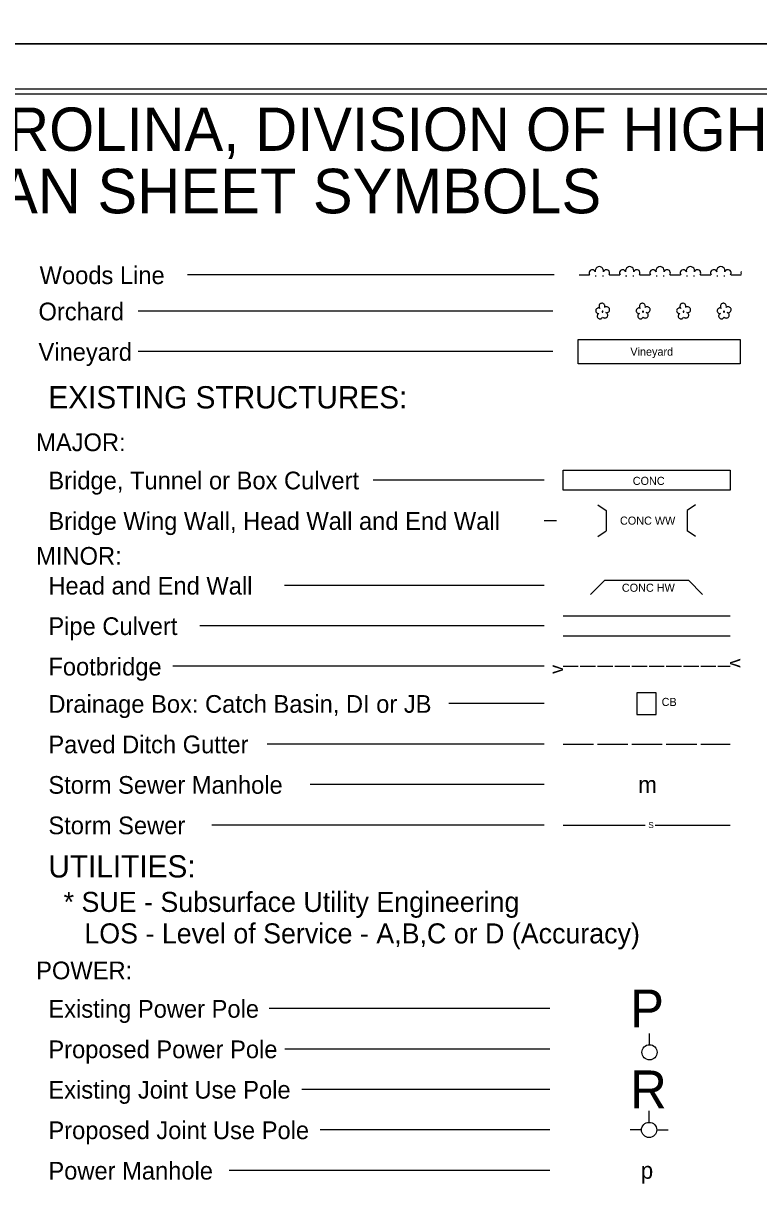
# Model space of a CAD drawing. Extents: x 925297 to 940193, y 663541 to 689899.
# Drawn here: x 932679 to 935584, y 667786 to 672419 of the extents above; entities that cross this region are included whole.
import ezdxf

# ---------------------------------------------------------------- set-up
doc = ezdxf.new("R2010")
doc.units = 0
for name, color, linetype in [('Sheet Cutting Line CELL', 7, 'Continuous'), ('Sheet Plot Border Inside CELL', 7, 'Continuous'), ('Sheet Plot Border Outside CELL', 7, 'Continuous'), ('Sheet Symbology CELL', 7, 'Continuous')]:
    doc.layers.add(name, color=color, linetype=linetype)

msp = doc.modelspace()

# ---------------------------------------------------------------- linework, layer by layer
at = {"layer": 'Sheet Cutting Line CELL'}
msp.add_line((938764.7, 672338.7), (925296.7, 672338.7), dxfattribs=at)
at = {"layer": 'Sheet Plot Border Inside CELL'}
msp.add_lwpolyline([(925400.7, 663720.9), (938728.7, 663720.9), (938728.7, 672159.2), (925400.7, 672159.2)], close=True, dxfattribs=at)
at = {"layer": 'Sheet Plot Border Outside CELL'}
for points in [[(925296.7, 672338.7), (938764.7, 672338.7), (938764.7, 681098.7), (925296.7, 681098.7)], [(925296.7, 663541.3), (938764.7, 663541.3), (938764.7, 672338.7), (925296.7, 672338.7)]]:
    msp.add_lwpolyline(points, close=True, dxfattribs=at)
at = {"layer": 'Sheet Symbology CELL'}
for p, q in [((934776, 671424.9), (933327.4, 671424.9)), ((934875.1, 671424.9), (934915.1, 671424.9)), ((934938.7, 671420.9), (934942.7, 671420.9)), ((934966.7, 671420.9), (934970.7, 671420.9)), ((934995, 671424.9), (935035, 671424.9)), ((935058.6, 671420.9), (935062.6, 671420.9)), ((935086.6, 671420.9), (935090.6, 671420.9)), ((935115, 671424.9), (935155, 671424.9)), ((935178.6, 671420.9), (935182.6, 671420.9)), ((935206.6, 671420.9), (935210.6, 671420.9)), ((935235, 671424.9), (935275, 671424.9)), ((935298.6, 671420.9), (935302.6, 671420.9)), ((935326.5, 671420.9), (935330.5, 671420.9)), ((935354.9, 671424.9), (935394.9, 671424.9)), ((935418.5, 671420.9), (935422.5, 671420.9)), ((935446.5, 671420.9), (935450.5, 671420.9)), ((935474.9, 671424.9), (935514.9, 671424.9)), ((934771.4, 671281.5), (933132.4, 671281.5)), ((934771.4, 671121.5), (933132.4, 671121.5)), ((934736.9, 670613.6), (934061.7, 670613.6)), ((934948.5, 670516.6), (934981.3, 670493.7)), ((935334, 670516.6), (935301.2, 670493.7)), ((934981.3, 670493.7), (934981.3, 670413.7)), ((935301.2, 670493.7), (935301.2, 670413.7)), ((934736.9, 670453.7), (934784.8, 670453.7)), ((934948.5, 670390.8), (934981.3, 670413.7)), ((935334, 670390.8), (935301.2, 670413.7)), ((934736.9, 670197.8), (933710.8, 670197.8)), ((934919.7, 670161.2), (934976.3, 670217.8)), ((934976.3, 670217.8), (935306.2, 670217.8)), ((935306.2, 670217.8), (935362.7, 670161.2)), ((934811.3, 670077.8), (935471.1, 670077.8)), ((934736.9, 670037.9), (933375.8, 670037.9)), ((934811.3, 669997.9), (935471.1, 669997.9)), ((934736.9, 669877.9), (933269.6, 669877.9)), ((934811.3, 669877.9), (934871.3, 669877.9)), ((934879.3, 669877.9), (934939.3, 669877.9)), ((934947.3, 669877.9), (935007.3, 669877.9)), ((935015.3, 669877.9), (935075.2, 669877.9)), ((935083.2, 669877.9), (935143.2, 669877.9)), ((935151.2, 669877.9), (935211.2, 669877.9)), ((935219.2, 669877.9), (935279.2, 669877.9)), ((935287.2, 669877.9), (935347.2, 669877.9)), ((935355.2, 669877.9), (935415.1, 669877.9)), ((935423.1, 669877.9), (935471.1, 669877.9)), ((934736.9, 669730.5), (934359.4, 669730.5)), ((934736.9, 669570.5), (933641.7, 669570.5)), ((934811.3, 669570.5), (934931.3, 669570.5)), ((934947.3, 669570.5), (935067.2, 669570.5)), ((935083.2, 669570.5), (935203.2, 669570.5)), ((935219.2, 669570.5), (935339.2, 669570.5)), ((935355.2, 669570.5), (935471.1, 669570.5)), ((934736.9, 669410.6), (933811.8, 669410.6)), ((934736.9, 669250.6), (933423.7, 669250.6)), ((934811.3, 669250.6), (935135.4, 669250.6)), ((935175.4, 669250.6), (935471.1, 669250.6)), ((934759.2, 668525.4), (933650, 668525.4)), ((935152.9, 668382.3), (935152.9, 668427.3)), ((934759.2, 668365.4), (933712.2, 668365.4)), ((934759.2, 668205.5), (933779.4, 668205.5)), ((935151.2, 668075.6), (935151.2, 668120.6)), ((934759.2, 668045.5), (933851.4, 668045.5)), ((935121.2, 668045.6), (935076.2, 668045.6)), ((935181.2, 668045.6), (935226.2, 668045.6)), ((934759.2, 667885.6), (933491.6, 667885.6))]:
    msp.add_line(p, q, dxfattribs=at)
for points in [[(938628.7, 672138.8), (926632.3, 672138.8), (926632.3, 663749.4), (938628.7, 663749.4)], [(935102.7, 669688), (935179.6, 669688), (935179.6, 669773), (935102.7, 669773)]]:
    msp.add_lwpolyline(points, close=True, dxfattribs=at)
for points in [[(934974.9, 671295.5), (934976.1, 671297.9), (934976.5, 671300.3), (934976.1, 671302.7), (934975.7, 671305.1), (934974.5, 671307.1), (934973.3, 671309.1), (934971.3, 671310.7), (934969.3, 671311.9), (934966.5, 671312.7), (934964.5, 671312.7), (934962.1, 671312.3), (934959.7, 671311.5), (934957.7, 671310.3), (934955.7, 671308.7), (934954.5, 671306.3), (934953.7, 671304.3), (934953.3, 671301.9), (934953.3, 671299.5), (934953.7, 671297.1), (934954.9, 671295.1), (934956.5, 671292.7), (934954.5, 671293.9), (934952.1, 671294.3), (934949.7, 671294.3), (934947.7, 671293.5), (934945.7, 671292.7), (934943.7, 671291.1), (934942.1, 671289.5), (934940.9, 671287.5), (934940.5, 671285.5), (934940.1, 671282.7), (934940.5, 671280.7), (934941.3, 671278.7), (934942.9, 671276.7), (934944.1, 671275.1), (934946.1, 671273.9), (934948.5, 671272.7), (934950.5, 671272.3), (934952.9, 671272.3), (934950.9, 671271.5), (934948.9, 671269.9), (934947.7, 671268.3), (934946.9, 671265.9), (934946.1, 671263.5), (934946.1, 671261.5), (934946.5, 671259.1), (934947.7, 671257.1), (934948.9, 671255.1), (934950.5, 671253.5), (934952.5, 671252.3), (934954.5, 671251.5), (934956.9, 671251.5), (934959.3, 671251.5), (934961.3, 671251.9), (934963.3, 671253.5), (934965.3, 671254.7), (934967.3, 671258.3)], [(935134.9, 671295.5), (935136.1, 671297.9), (935136.5, 671300.3), (935136.1, 671302.7), (935135.7, 671305.1), (935134.5, 671307.1), (935133.3, 671309.1), (935131.3, 671310.7), (935129.3, 671311.9), (935126.5, 671312.7), (935124.5, 671312.7), (935122.1, 671312.3), (935119.7, 671311.5), (935117.7, 671310.3), (935115.7, 671308.7), (935114.5, 671306.3), (935113.7, 671304.3), (935113.3, 671301.9), (935113.3, 671299.5), (935113.7, 671297.1), (935114.9, 671295.1), (935116.5, 671292.7), (935114.5, 671293.9), (935112.1, 671294.3), (935109.7, 671294.3), (935107.7, 671293.5), (935105.7, 671292.7), (935103.7, 671291.1), (935102.1, 671289.5), (935100.9, 671287.5), (935100.5, 671285.5), (935100.1, 671282.7), (935100.5, 671280.7), (935101.3, 671278.7), (935102.9, 671276.7), (935104.1, 671275.1), (935106.1, 671273.9), (935108.5, 671272.7), (935110.5, 671272.3), (935112.9, 671272.3), (935110.9, 671271.5), (935108.9, 671269.9), (935107.7, 671268.3), (935106.9, 671265.9), (935106.1, 671263.5), (935106.1, 671261.5), (935106.5, 671259.1), (935107.7, 671257.1), (935108.9, 671255.1), (935110.5, 671253.5), (935112.5, 671252.3), (935114.5, 671251.5), (935116.9, 671251.5), (935119.3, 671251.5), (935121.3, 671251.9), (935123.3, 671253.5), (935125.3, 671254.7), (935127.3, 671258.3)], [(935294.8, 671295.5), (935296, 671297.9), (935296.4, 671300.3), (935296, 671302.7), (935295.6, 671305.1), (935294.4, 671307.1), (935293.2, 671309.1), (935291.2, 671310.7), (935289.2, 671311.9), (935286.4, 671312.7), (935284.4, 671312.7), (935282, 671312.3), (935279.6, 671311.5), (935277.6, 671310.3), (935275.6, 671308.7), (935274.4, 671306.3), (935273.6, 671304.3), (935273.2, 671301.9), (935273.2, 671299.5), (935273.6, 671297.1), (935274.8, 671295.1), (935276.4, 671292.7), (935274.4, 671293.9), (935272, 671294.3), (935269.6, 671294.3), (935267.6, 671293.5), (935265.6, 671292.7), (935263.6, 671291.1), (935262, 671289.5), (935260.8, 671287.5), (935260.4, 671285.5), (935260, 671282.7), (935260.4, 671280.7), (935261.2, 671278.7), (935262.8, 671276.7), (935264, 671275.1), (935266, 671273.9), (935268.4, 671272.7), (935270.4, 671272.3), (935272.8, 671272.3), (935270.8, 671271.5), (935268.8, 671269.9), (935267.6, 671268.3), (935266.8, 671265.9), (935266, 671263.5), (935266, 671261.5), (935266.4, 671259.1), (935267.6, 671257.1), (935268.8, 671255.1), (935270.4, 671253.5), (935272.4, 671252.3), (935274.4, 671251.5), (935276.8, 671251.5), (935279.2, 671251.5), (935281.2, 671251.9), (935283.2, 671253.5), (935285.2, 671254.7), (935287.2, 671258.3)], [(935454.8, 671295.5), (935456, 671297.9), (935456.4, 671300.3), (935456, 671302.7), (935455.6, 671305.1), (935454.4, 671307.1), (935453.2, 671309.1), (935451.2, 671310.7), (935449.2, 671311.9), (935446.4, 671312.7), (935444.4, 671312.7), (935442, 671312.3), (935439.6, 671311.5), (935437.6, 671310.3), (935435.6, 671308.7), (935434.4, 671306.3), (935433.6, 671304.3), (935433.2, 671301.9), (935433.2, 671299.5), (935433.6, 671297.1), (935434.8, 671295.1), (935436.4, 671292.7), (935434.4, 671293.9), (935432, 671294.3), (935429.6, 671294.3), (935427.6, 671293.5), (935425.6, 671292.7), (935423.6, 671291.1), (935422, 671289.5), (935420.8, 671287.5), (935420.4, 671285.5), (935420, 671282.7), (935420.4, 671280.7), (935421.2, 671278.7), (935422.8, 671276.7), (935424, 671275.1), (935426, 671273.9), (935428.4, 671272.7), (935430.4, 671272.3), (935432.8, 671272.3), (935430.8, 671271.5), (935428.8, 671269.9), (935427.6, 671268.3), (935426.8, 671265.9), (935426, 671263.5), (935426, 671261.5), (935426.4, 671259.1), (935427.6, 671257.1), (935428.8, 671255.1), (935430.4, 671253.5), (935432.4, 671252.3), (935434.4, 671251.5), (935436.8, 671251.5), (935439.2, 671251.5), (935441.2, 671251.9), (935443.2, 671253.5), (935445.2, 671254.7), (935447.2, 671258.3)], [(934968.1, 671281.5), (934966.9, 671281.5), (934966.1, 671281.1), (934965.3, 671280.7), (934965.3, 671279.5), (934965.3, 671278.7), (934966.1, 671277.9), (934967.3, 671277.9), (934968.1, 671277.9), (934968.9, 671278.7), (934969.3, 671279.9), (934968.9, 671280.7), (934968.1, 671281.5)], [(934967.3, 671258.3), (934972.1, 671255.5), (934974.5, 671254.7), (934976.9, 671254.3), (934979.3, 671254.7), (934981.3, 671255.5), (934983.3, 671256.7), (934985.3, 671258.3), (934986.5, 671260.3), (934987.3, 671262.3), (934988.1, 671264.7), (934987.7, 671267.1), (934987.3, 671269.5), (934985.7, 671271.9), (934984.5, 671273.5), (934982.5, 671274.7), (934980.1, 671275.9), (934982.5, 671275.5), (934985.3, 671275.5), (934987.3, 671276.3), (934989.7, 671277.5), (934991.7, 671278.7), (934993.3, 671280.7), (934994.5, 671283.1), (934994.9, 671285.5), (934995.3, 671287.9), (934994.9, 671290.3), (934994.1, 671292.7), (934992.5, 671294.7), (934990.5, 671296.7), (934988.5, 671297.9), (934986.1, 671298.7), (934983.7, 671299.1), (934981.3, 671299.1), (934978.9, 671298.3), (934976.9, 671297.1), (934974.9, 671295.5)], [(935128.1, 671281.5), (935126.9, 671281.5), (935126.1, 671281.1), (935125.3, 671280.7), (935125.3, 671279.5), (935125.3, 671278.7), (935126.1, 671277.9), (935127.3, 671277.9), (935128.1, 671277.9), (935128.9, 671278.7), (935129.3, 671279.9), (935128.9, 671280.7), (935128.1, 671281.5)], [(935127.3, 671258.3), (935132.1, 671255.5), (935134.5, 671254.7), (935136.9, 671254.3), (935139.3, 671254.7), (935141.3, 671255.5), (935143.3, 671256.7), (935145.3, 671258.3), (935146.5, 671260.3), (935147.3, 671262.3), (935148.1, 671264.7), (935147.7, 671267.1), (935147.3, 671269.5), (935145.7, 671271.9), (935144.5, 671273.5), (935142.5, 671274.7), (935140.1, 671275.9), (935142.5, 671275.5), (935145.3, 671275.5), (935147.3, 671276.3), (935149.7, 671277.5), (935151.7, 671278.7), (935153.3, 671280.7), (935154.5, 671283.1), (935154.9, 671285.5), (935155.3, 671287.9), (935154.9, 671290.3), (935154.1, 671292.7), (935152.5, 671294.7), (935150.5, 671296.7), (935148.5, 671297.9), (935146.1, 671298.7), (935143.7, 671299.1), (935141.3, 671299.1), (935138.9, 671298.3), (935136.9, 671297.1), (935134.9, 671295.5)], [(935288, 671281.5), (935286.8, 671281.5), (935286, 671281.1), (935285.2, 671280.7), (935285.2, 671279.5), (935285.2, 671278.7), (935286, 671277.9), (935287.2, 671277.9), (935288, 671277.9), (935288.8, 671278.7), (935289.2, 671279.9), (935288.8, 671280.7), (935288, 671281.5)], [(935287.2, 671258.3), (935292, 671255.5), (935294.4, 671254.7), (935296.8, 671254.3), (935299.2, 671254.7), (935301.2, 671255.5), (935303.2, 671256.7), (935305.2, 671258.3), (935306.4, 671260.3), (935307.2, 671262.3), (935308, 671264.7), (935307.6, 671267.1), (935307.2, 671269.5), (935305.6, 671271.9), (935304.4, 671273.5), (935302.4, 671274.7), (935300, 671275.9), (935302.4, 671275.5), (935305.2, 671275.5), (935307.2, 671276.3), (935309.6, 671277.5), (935311.6, 671278.7), (935313.2, 671280.7), (935314.4, 671283.1), (935314.8, 671285.5), (935315.2, 671287.9), (935314.8, 671290.3), (935314, 671292.7), (935312.4, 671294.7), (935310.4, 671296.7), (935308.4, 671297.9), (935306, 671298.7), (935303.6, 671299.1), (935301.2, 671299.1), (935298.8, 671298.3), (935296.8, 671297.1), (935294.8, 671295.5)], [(935448, 671281.5), (935446.8, 671281.5), (935446, 671281.1), (935445.2, 671280.7), (935445.2, 671279.5), (935445.2, 671278.7), (935446, 671277.9), (935447.2, 671277.9), (935448, 671277.9), (935448.8, 671278.7), (935449.2, 671279.9), (935448.8, 671280.7), (935448, 671281.5)], [(935447.2, 671258.3), (935452, 671255.5), (935454.4, 671254.7), (935456.8, 671254.3), (935459.2, 671254.7), (935461.2, 671255.5), (935463.2, 671256.7), (935465.2, 671258.3), (935466.4, 671260.3), (935467.2, 671262.3), (935468, 671264.7), (935467.6, 671267.1), (935467.2, 671269.5), (935465.6, 671271.9), (935464.4, 671273.5), (935462.4, 671274.7), (935460, 671275.9), (935462.4, 671275.5), (935465.2, 671275.5), (935467.2, 671276.3), (935469.6, 671277.5), (935471.6, 671278.7), (935473.2, 671280.7), (935474.4, 671283.1), (935474.8, 671285.5), (935475.2, 671287.9), (935474.8, 671290.3), (935474, 671292.7), (935472.4, 671294.7), (935470.4, 671296.7), (935468.4, 671297.9), (935466, 671298.7), (935463.6, 671299.1), (935461.2, 671299.1), (935458.8, 671298.3), (935456.8, 671297.1), (935454.8, 671295.5)], [(934870.6, 671169.5), (935510.4, 671169.5), (935510.4, 671073.6), (934870.6, 671073.6), (934870.6, 671169.5)], [(934811.3, 670653.6), (935471.1, 670653.6), (935471.1, 670573.7), (934811.3, 670573.7), (934811.3, 670653.6)]]:
    msp.add_lwpolyline(points, dxfattribs=at)
for centre in [(935152.9, 668352.3), (935151.2, 668045.5)]:
    msp.add_circle(centre, 30, dxfattribs=at)
for centre, radius, start, end in [((934926.7, 671433), 12.6, 18.435, 219.2315), ((934954.7, 671441), 16.5, 345.9638, 194.0362), ((934982.6, 671433), 12.6, 320.7685, 161.5651), ((935046.6, 671433), 12.6, 18.435, 219.2315), ((935074.6, 671441), 16.5, 345.9638, 194.0362), ((935102.6, 671433), 12.6, 320.7685, 161.5651), ((935166.6, 671433), 12.6, 18.435, 219.2315), ((935194.6, 671441), 16.5, 345.9638, 194.0362), ((935222.6, 671433), 12.6, 320.7685, 161.5651), ((935286.5, 671433), 12.6, 18.435, 219.2315), ((935314.5, 671441), 16.5, 345.9638, 194.0362), ((935342.5, 671433), 12.6, 320.7685, 161.5651), ((935406.5, 671433), 12.6, 18.435, 219.2315), ((935434.5, 671441), 16.5, 345.9638, 194.0362), ((935462.5, 671433), 12.6, 320.7685, 161.5651), ((935526.5, 671433), 12.6, 156.251, 203.749)]:
    msp.add_arc(centre, radius, start, end, dxfattribs=at)

# ---------------------------------------------------------------- texts
for s, height, p in [('STATE OF NORTH CAROLINA, DIVISION OF HIGHWAYS', 171.301, (930235.7, 671915.2)), ('CONVENTIONAL  PLAN SHEET SYMBOLS', 176.206, (930300.7, 671668.2)), ('Woods Line', 69.98, (932743.3, 671388.7)), ('Orchard', 69.98, (932738.8, 671245.3)), ('Vineyard', 69.98, (932738.8, 671085.4)), ('EXISTING STRUCTURES:', 87.974, (932777.8, 670897.2)), ('MAJOR:', 69.98, (932729.6, 670728.3)), ('Bridge, Tunnel or Box Culvert', 69.979, (932777.8, 670577.3)), ('CONC', 31.99, (935086.7, 670594.8)), ('Bridge Wing Wall, Head Wall and End Wall', 69.979, (932777.8, 670417.3)), ('MINOR:', 69.98, (932729.6, 670279.4)), ('Head and End Wall', 69.979, (932777.8, 670161.4)), ('Pipe Culvert', 69.979, (932777.8, 670001.6)), ('Footbridge', 69.98, (932777.9, 669841.6)), ('Drainage Box: Catch Basin, DI or JB', 69.979, (932777.9, 669694.2)), ('Paved Ditch Gutter', 69.979, (932777.9, 669534.1)), ('Storm Sewer Manhole', 69.979, (932777.9, 669374.2)), ('m', 66, (935108.2, 669377.6)), ('Storm Sewer', 69.979, (932777.9, 669214.2)), ('S', 24, (935148.2, 669238.6)), ('UTILITIES:', 87.97, (932777.8, 669043.3)), ('POWER:', 69.98, (932729.6, 668641)), ('P', 150, (935076.2, 668450.4)), ('Existing Power Pole', 69.979, (932777.9, 668489.1)), ('Proposed Power Pole', 69.979, (932777.9, 668329.1)), ('R', 150, (935076.2, 668130.5)), ('Existing Joint Use Pole', 69.979, (932777.9, 668169.3)), ('Proposed Joint Use Pole', 69.979, (932778, 668009.2)), ('Power Manhole', 69.979, (932778, 667849.3)), ('p', 66, (935118.2, 667852.6))]:
    msp.add_text(s, height=height, dxfattribs=at).set_placement(p)
for s, height, rotation, p in [('Vineyard', 31.99, 0, (935077.1, 671105.5)), ('CONC WW', 31.99, 0, (935036.2, 670437.7)), ('CONC HW', 31.99, 360, (935043.6, 670172.5)), ('v', 52.8, 89.7591, (934811.2, 669848)), ('v', 52.8, 270.2409, (935471, 669907.8)), ('CB', 31.99, 360, (935200.7, 669721.1)), ('* SUE - Subsurface Utility Engineering', 79.177, 360, (932838.1, 668907.2)), ('LOS - Level of Service - A,B,C or D (Accuracy) ', 79.177, 360, (932920.2, 668782.7))]:
    msp.add_text(s, height=height, rotation=rotation, dxfattribs=at).set_placement(p)

doc.saveas('drawing.dxf')
